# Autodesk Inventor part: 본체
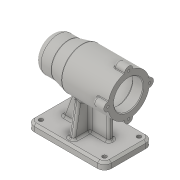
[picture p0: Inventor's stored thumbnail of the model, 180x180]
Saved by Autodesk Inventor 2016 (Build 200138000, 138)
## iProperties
Created: 2019-07
Part Number: 본체
Material: 일반
Document SubType Name: Modeling
Designer: 3sil_cad0123
Density: 1 g/cm^3
Appearance: 기본값
Author: 3sil_cad0123
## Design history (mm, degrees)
sketch "스케치1"
  geometry: L1 (56, 35)-(-56, 35); L2 (-56, 35)-(-56, -35); L3 (-56, -35)-(56, -35); L4 (56, -35)-(56, 35); L5 (56, 35)-(-56, -35); L6 (-56, 35)-(56, -35); 1 further point
  constraints: 12 end point, 2 midpoint, 2 parallel, 1 horizontal, 1 perpendicular
  dimensions: "d0" = 112 distance of L2.end L3.end; "d1" = 70 distance of L1.end L2.end
extrude "돌출1" new body sketch "스케치1" distance "d2" = 10; taper "d3" = 0 deg
sketch "스케치2"
  geometry: L1 (-56, 80)-(56, 80); L2 (56, 80)-(56, 105); L3 (56, 105)-(-56, 105); L4 (-56, 105)-(-56, 80); L5 (-56, 80)-(56, 105); L6 (56, 80)-(-56, 105); L7 (-56, 0)-(56, 0) reference; L8 (-31, 105)-(-11, 110); L9 (-11, 110)-(56, 110); L10 (56, 110)-(56, 105); 4 further points
  constraints: 18 end point, 4 midpoint, 2 horizontal, 2 parallel, 2 perpendicular, 1 point on line, 1 vertical alignment
  dimensions: "d4" = 112 distance of L2.end L3.end; "d5" = 50 diameter of L3 L1; "d7" = 25 distance of L3.end L8.start; "d8" = 45 horizontal distance of L3.end L8.end; "d9" = 60 diameter of L9 L1; "d87" = 80 distance from line of L7 L1.end
revolve "회전1" sketch "스케치2" stored, may be unused: angle "d10" = 90 deg
sketch "스케치3"
  geometry: L1 (-56, 55)-(-56, 105) reference; L2 (56, 50)-(56, 110) reference; L3 (56, 80)-(41, 80); L4 (41, 80)-(41, 101); L5 (41, 101)-(56, 101); L6 (56, 101)-(56, 80); L7 (41, 80)-(-13, 80); L8 (-13, 80)-(-13, 104); L9 (-13, 104)-(41, 104); L10 (41, 104)-(41, 80); L11 (-13, 80)-(-25, 80); L12 (-25, 80)-(-25, 101); L13 (-25, 101)-(-13, 101); L14 (-13, 101)-(-13, 80); L15 (-25, 80)-(-43, 80); L16 (-43, 80)-(-43, 97.5); L17 (-43, 97.5)-(-25, 97.5); L18 (-25, 97.5)-(-25, 80); L19 (-43, 80)-(-47, 80); L20 (-47, 80)-(-47, 96); L21 (-47, 96)-(-43, 96); L22 (-43, 96)-(-43, 80); L23 (-47, 80)-(-50, 80); L24 (-50, 80)-(-50, 90.5); L25 (-50, 90.5)-(-47, 90.5); L26 (-47, 90.5)-(-47, 80); 1 further point
  constraints: 48 end point, 13 parallel, 6 horizontal, 6 perpendicular, 1 midpoint
  dimensions: "d11" = 15 distance of L4.end L5.end; "d14" = 54 distance of L8.end L9.end; "d16" = 12 distance of L12.end L13.end; "d17" = 18 distance of L16.end L17.end; "d19" = 4 distance of L20.end L21.end; "d21" = 3 distance of L24.end L25.end; "d23" = 42 diameter of L5 L3; "d24" = 48 diameter of L9 L7; "d25" = 35 diameter of L17 L15; "d26" = 32 diameter of L21 L19; "d27" = 21 diameter of L25 L23
revolve "회전2" sketch "스케치3" stored, may be unused: angle "d28" = 90 deg
sketch "스케치4"
  geometry: L1 (56, -35)-(56, 35) reference; L2 (0, -4)-(31, -4); L3 (31, -4)-(31, 4); L4 (31, 4)-(0, 4); L5 (0, 4)-(0, -4); L6 (0, -4)-(31, 4); L7 (31, -4)-(0, 4); 3 further points
  constraints: 12 end point, 4 midpoint, 2 parallel, 1 horizontal, 1 horizontal alignment, 1 perpendicular
  dimensions: "d29" = 8 distance of L2.end L3.end; "d30" = 25 distance between parallel lines of L1 L3
extrude "돌출2" join sketch "스케치4" stored distance "d31" = 10; taper "d32" = 0 deg
sketch "스케치5"
  geometry: L1 (-36, 10)-(-28.89, 29.536); L2 (-56, 10)-(56, 10) reference; L3 (-56, 0)-(-56, 10) reference; 1 further point
  constraints: 2 end point, 1 point on line
  dimensions: "d33" = 110 deg angle of L2 L1; "d34" = 20 distance from line of L3 L1.start
feature "리브1" sketch "스케치5" dims "d35" = 1, "d36" = 8, "d37" = 0, "d38" = 0, "d39" = 1, "d40" = 1
sketch "스케치6"
  geometry: L1 (10, -28)-(27.314, -24.947); L2 (10, 35)-(10, -35) reference; L3 (0, -35)-(10, -35) reference; 1 further point
  constraints: 2 end point, 1 point on line
  dimensions: "d41" = 100 deg angle of L2 L1; "d42" = 7 distance from line of L3 L1.start
feature "리브2" sketch "스케치6" dims "d43" = 1, "d44" = 8, "d45" = 0, "d46" = 0, "d47" = 1, "d48" = 1
sketch "스케치7"
  geometry: L1 (56, 50)-(56, 110) reference; L2 (56, 110)-(40, 110); L3 (40, 110)-(40, 116); L4 (40, 116)-(56, 116); L5 (56, 116)-(56, 110); 1 further point
  constraints: 8 end point, 2 parallel, 1 horizontal, 1 perpendicular
  dimensions: "d49" = 16 distance of L3.end L4.end; "d50" = 12 diameter of L4 L2
revolve "회전3" sketch "스케치7" stored, may be unused: angle "d51" = 90 deg
sketch "스케치8"
  geometry: A1 r 6 centre (0, 30) between (5.97, 29.4) and (-5.97, 29.4) reference; 2 further points
  constraints: 1 coincident
hole "구멍1" sketch "스케치8" at (0, 30) diameter "d52" = 3.242; stored, may be unused: countersink angle "d56" = 90 deg, drill point angle "d58" = 118 deg; dims "d53" = 8, "d54" = 4, "d55" = 2, "d57" = 11
fillet "모깎기1" dims "d62" = 10
sketch "스케치9"
  geometry: A1 r 10 centre (-46, 25) between (-46, 35) and (-56, 25) reference; A2 r 10 centre (-46, -25) between (-56, -25) and (-46, -35) reference; A3 r 10 centre (46, -25) between (46, -35) and (56, -25) reference; A4 r 10 centre (46, 25) between (56, 25) and (46, 35) reference; 5 further points
  constraints: 4 coincident
hole "구멍2" sketch "스케치9" at (-46, 25), (46, 25), (46, -25), (-46, -25) diameter "d63" = 6; stored, may be unused: countersink angle "d67" = 90 deg, drill point angle "d69" = 0 deg; dims "d64" = 8, "d65" = 4, "d66" = 2, "d68" = 11
fillet "모깎기2" dims "d70" = 0.3
fillet "모깎기3" dims "d71" = 3
fillet "모깎기4" dims "d72" = 10
fillet "모깎기5" dims "d73" = 3
fillet "모깎기6" dims "d74" = 1
chamfer "모따기1" distance "d75" = 1; stored, may be unused: second distance "d76" = 2, angle "d77" = 45 deg
chamfer "모따기2" distance "d78" = 3; stored, may be unused: second distance "d79" = 2, angle "d80" = 45 deg
fillet "모깎기7" dims "d81" = 3
fillet "모깎기8" dims "d82" = 3
fillet "모깎기9" dims "d83" = 3
fillet "모깎기10" dims "d88" = 3
node "작업 평면1"
sketch "스케치10"
  geometry: L1 (33.5, 30.171)-(33.5, 36) reference; L2 (33.5, -5.998)-(33.5, 5.998) reference; 3 further points
  constraints: 1 horizontal alignment, 1 midpoint, 1 other
  dimensions: "d84" = 42 distance from line of L1 point (-8.5, 0)
feature "엠보싱1" sketch "스케치10" dims "d0" = 112, "d1" = 70, "d10" = 90 deg, "d85" = 0.5, "d86" = 0
node "솔리드1"
mirror "대칭1"
pattern_circular "원형 패턴1" dims angle "d60" = 360 deg
